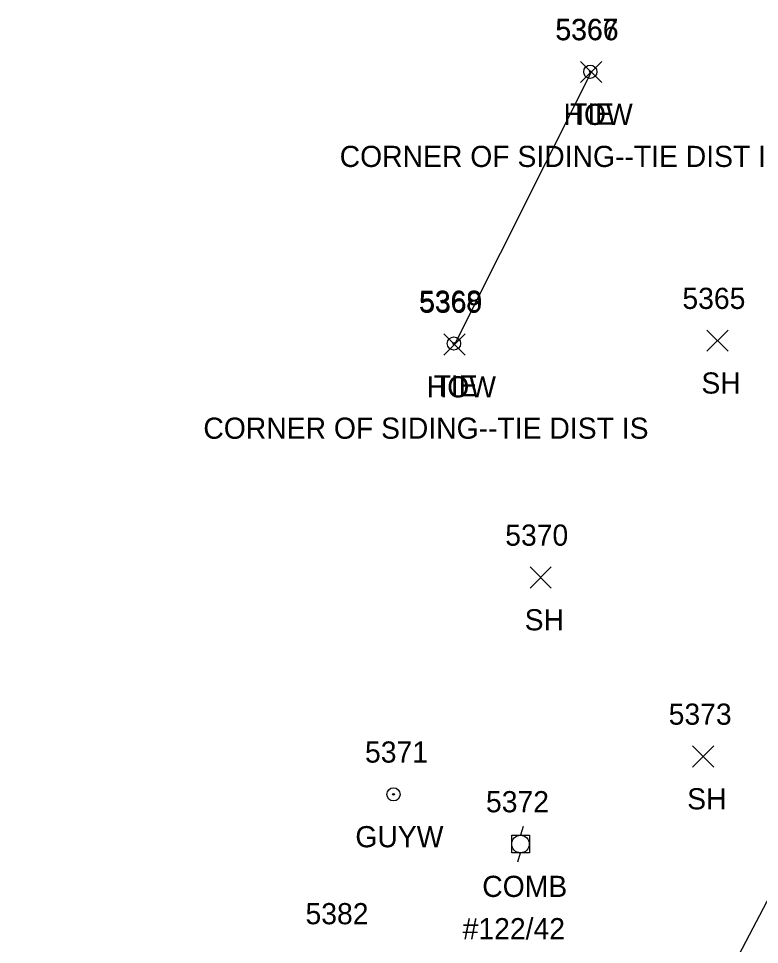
# Model space of a CAD drawing. Extents: x 1678863 to 1683592, y 407783 to 418211.
# Drawn here: x 1679703.8 to 1679773.8, y 411490.3 to 411577.8 of the extents above; entities that cross this region are included whole.
import ezdxf

# ---------------------------------------------------------------- set-up
doc = ezdxf.new("R2010")
doc.units = 0
for name, color, linetype in [('C_A', 7, 'Continuous'), ('C_C', 7, 'Continuous'), ('C_I', 7, 'Continuous'), ('CBP', 7, 'Continuous'), ('L_A', 7, 'Continuous'), ('L_I', 7, 'Continuous'), ('L_TIC', 7, 'Continuous'), ('LBC', 7, 'Continuous'), ('LELB', 7, 'Continuous'), ('U_A', 7, 'Continuous'), ('U_C', 7, 'Continuous'), ('U_I', 7, 'Continuous'), ('UP', 7, 'Continuous'), ('UPGW', 7, 'Continuous')]:
    doc.layers.add(name, color=color, linetype=linetype)

msp = doc.modelspace()

# ---------------------------------------------------------------- linework, layer by layer
at = {"layer": 'CBP'}
for centre, radius in [((1679757.781, 411572.743), 0.625), ((1679757.781, 411572.743), 0.0833), ((1679744.901, 411547.058), 0.625), ((1679744.901, 411547.058), 0.0833)]:
    msp.add_circle(centre, radius, dxfattribs=at)
at = {"layer": 'L_TIC'}
for points in [[(1679756.868, 411571.717), (1679758.868, 411573.717)], [(1679758.868, 411571.717), (1679756.868, 411573.717)], [(1679743.953, 411545.965), (1679745.953, 411547.965)], [(1679745.953, 411545.965), (1679743.953, 411547.965)], [(1679768.788, 411546.327), (1679770.788, 411548.327)], [(1679770.788, 411546.327), (1679768.788, 411548.327)], [(1679752.094, 411523.952), (1679754.094, 411525.952)], [(1679754.094, 411523.952), (1679752.094, 411525.952)], [(1679767.444, 411507.035), (1679769.444, 411509.035)], [(1679769.444, 411507.035), (1679767.444, 411509.035)]]:
    msp.add_lwpolyline(points, dxfattribs=at)
at = {"layer": 'LBC'}
msp.add_lwpolyline([(1679757.868, 411572.717), (1679744.953, 411546.965)], dxfattribs=at)
at = {"layer": 'LELB'}
msp.add_lwpolyline([(1679806.135, 411547.446), (1679797.641, 411528.328), (1679778.356, 411501.748), (1679763.635, 411473.684), (1679746.029, 411447.883), (1679723.06, 411418.16), (1679702.434, 411379.457), (1679690.589, 411343.003), (1679675.582, 411304.579), (1679662.659, 411263.348), (1679652.178, 411219.732), (1679640.469, 411176.726), (1679632.707, 411132.013), (1679618.527, 411081.801), (1679605.347, 411027.527), (1679595.305, 410983.652), (1679573.884, 410936.553), (1679563.601, 410891.231), (1679557.656, 410846.462), (1679539.412, 410796.622)], dxfattribs=at)
at = {"layer": 'UP'}
for p, q in [((1679751.44, 411501.426), (1679751.19, 411500.593)), ((1679750.357, 411498.926), (1679750.357, 411500.593)), ((1679750.357, 411500.593), (1679752.024, 411500.593)), ((1679752.024, 411500.593), (1679752.024, 411498.926)), ((1679751.19, 411499.76), (1679751.19, 411499.76)), ((1679752.024, 411498.926), (1679750.357, 411498.926)), ((1679750.94, 411498.093), (1679751.19, 411498.926))]:
    msp.add_line(p, q, dxfattribs=at)
msp.add_circle((1679751.19, 411499.76), 0.833, dxfattribs=at)
at = {"layer": 'UPGW'}
for radius in [0.625, 0.0833]:
    msp.add_circle((1679739.195, 411504.454), radius, dxfattribs=at)

# ---------------------------------------------------------------- texts
at = {"layer": 'C_A'}
for p in [(1679755.86, 411567.743), (1679742.98, 411542.058)]:
    msp.add_text('TIE', height=2, dxfattribs=at).set_placement(p)
at = {"layer": 'C_C'}
for p in [(1679734.112, 411563.743), (1679721.232, 411538.058)]:
    msp.add_text('CORNER OF SIDING--TIE DIST IS', height=2, dxfattribs=at).set_placement(p)
at = {"layer": 'C_I'}
for s, p in [('5367', (1679754.474, 411575.743)), ('5368', (1679741.594, 411550.058))]:
    msp.add_text(s, height=2, dxfattribs=at).set_placement(p)
at = {"layer": 'L_A'}
for s, p in [('HOW', (1679755.253, 411567.717)), ('SH', (1679768.276, 411542.327)), ('HOW', (1679742.339, 411541.965)), ('SH', (1679751.582, 411519.952)), ('SH', (1679766.932, 411503.035))]:
    msp.add_text(s, height=2, dxfattribs=at).set_placement(p)
at = {"layer": 'L_I'}
for s, p in [('5366', (1679754.505, 411575.717)), ('5365', (1679766.481, 411550.327)), ('5369', (1679741.638, 411549.965)), ('5370', (1679749.748, 411527.952)), ('5373', (1679765.184, 411511.035)), ('5382', (1679730.883, 411492.179))]:
    msp.add_text(s, height=2, dxfattribs=at).set_placement(p)
at = {"layer": 'U_A'}
for s, p in [('GUYW', (1679735.589, 411499.454)), ('COMB', (1679747.576, 411494.76))]:
    msp.add_text(s, height=2, dxfattribs=at).set_placement(p)
at = {"layer": 'U_C'}
msp.add_text('#122/42', height=2, dxfattribs=at).set_placement((1679745.726, 411490.76))
at = {"layer": 'U_I'}
for s, p in [('5371', (1679736.502, 411507.454)), ('5372', (1679747.93, 411502.76))]:
    msp.add_text(s, height=2, dxfattribs=at).set_placement(p)

doc.saveas('drawing.dxf')
